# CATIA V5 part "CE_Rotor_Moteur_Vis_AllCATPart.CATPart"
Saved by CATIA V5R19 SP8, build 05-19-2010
Part number: CE9_Rotor_Moteur_Vis_AllCATPart
Bounding box of the stored display mesh (mm): x -103.461 to -69.464, y 117.118 to 181.07, z 26.73 to 111.597
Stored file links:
  D:\Documents\1_Travail\1 - ac-limoges.fr\ac-limoges.fr\Emmanuel Maynard - STI2D_Turgot\2 -2I2D\1_SEQUENCE_ Tapis_de_course\3- Spécificités\Spé_ITEC\3-Pente\Tapis_TC520B_Pente\CE_Rotor_Moteur_Vis_AllCATPart.CATPart
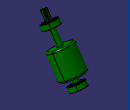
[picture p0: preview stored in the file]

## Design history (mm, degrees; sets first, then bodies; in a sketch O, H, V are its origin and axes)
AxisSystem1: origin (0, 0, 0), X (1, 0, 0), Y (0, 1, 0), Z (0, 0, 1)
Body1 (main body)
Body2 "snr_608zz_1_1.1"
  Solid1: solid without history
  Body3 "snr_608zz_1_1.1\\snr_608zz_1_2"
    Solid2 "Solide.1": solid without history
  Add1 "snr_608zz_1_1.1\\snr_608zz_1_2": tool Body3
  Body4 "snr_608zz_1_1.1\\snr_608zz_1_3"
    Solid3 "Solide.1": solid without history
  Add2 "snr_608zz_1_1.1\\snr_608zz_1_3": tool Body4
  Body5 "snr_608zz_1_1.1\\snr_608zz_1_4"
    Solid4 "Solide.1": solid without history
  Add3 "snr_608zz_1_1.1\\snr_608zz_1_4": tool Body5
  Body6 "snr_608zz_1_1.1\\snr_608zz_1_5"
    Solid5 "Solide.1": solid without history
  Add4 "snr_608zz_1_1.1\\snr_608zz_1_5": tool Body6
Body7 "Rotor_Moteur_Vis.1\\Corps principal"
  Solid6 "Solide.1": solid without history
Body8 "snr_608zz_1_1.2"
  Solid7 "Solide.1": solid without history
  Body9 "snr_608zz_1_1.2\\snr_608zz_1_2"
    Solid8 "Solide.1": solid without history
  Add5 "snr_608zz_1_1.2\\snr_608zz_1_2": tool Body9
  Body10 "snr_608zz_1_1.2\\snr_608zz_1_3"
    Solid9 "Solide.1": solid without history
  Add6 "snr_608zz_1_1.2\\snr_608zz_1_3": tool Body10
  Body11 "snr_608zz_1_1.2\\snr_608zz_1_4"
    Solid10 "Solide.1": solid without history
  Add7 "snr_608zz_1_1.2\\snr_608zz_1_4": tool Body11
  Body12 "snr_608zz_1_1.2\\snr_608zz_1_5"
    Solid11 "Solide.1": solid without history
  Add8 "snr_608zz_1_1.2\\snr_608zz_1_5": tool Body12
Body13 "ring_eantw7.1\\ring_eantw7"
  Solid12 "Solide.1": solid without history
Body14 "ring_eantw7.2\\ring_eantw7"
  Solid13 "Solide.1": solid without history
Body15 "Roue 1.1\\Corps principal"
  Solid14 "Solide.1": solid without history
  Plane1 "Plan.2": stored without definition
